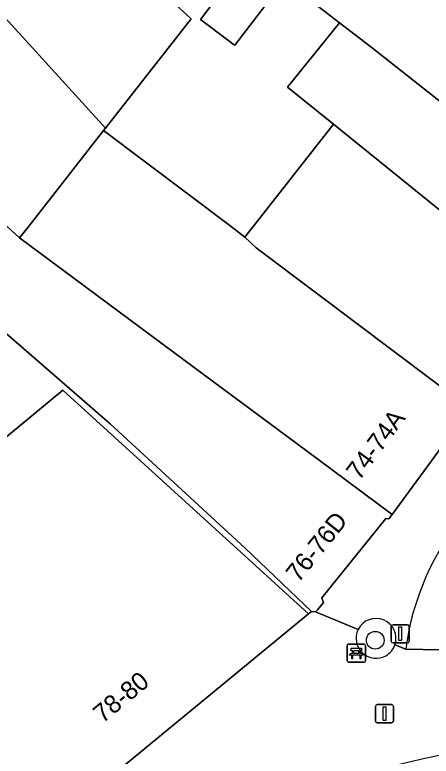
# Model space of a CAD drawing. Extents: x 160663 to 161506, y 382245 to 383291.
# Drawn here: x 160983.36 to 161006.23, y 382930.82 to 382971.53 of the extents above; entities that cross this region are included whole.
import ezdxf

# ---------------------------------------------------------------- set-up
doc = ezdxf.new("R2010")
doc.units = 0
for name, color, linetype in [('IMGEO_Bank', 7, 'Continuous'), ('IMGEO_Boom', 7, 'Continuous'), ('IMGEO_Erf', 7, 'Continuous'), ('IMGEO_Groenvoorziening', 7, 'Continuous'), ('IMGEO_Pand', 7, 'Continuous'), ('IMGEO_Pand_nummerreeks', 7, 'Continuous'), ('IMGEO_Rijbaan_lokaal_gesloten', 7, 'Continuous'), ('IMGEO_Verkeersregelinstallatiepaal', 7, 'Continuous'), ('IMGEO_Voetpad_open', 7, 'Continuous'), ('IMGEO_Woonerf_open', 7, 'Continuous')]:
    doc.layers.add(name, color=color, linetype=linetype)

msp = doc.modelspace()

# ---------------------------------------------------------------- linework, layer by layer
at = {"layer": 'IMGEO_Bank'}
for p, q in [((161001.621, 382936.055), (161001.621, 382936.896)), ((161001.621, 382936.896), (161001.621, 382936.055)), ((161001.696, 382936.98), (161002.537, 382936.98)), ((161002.537, 382936.98), (161001.696, 382936.98)), ((161002.621, 382936.905), (161002.621, 382936.064)), ((161002.621, 382936.064), (161002.621, 382936.905)), ((161001.93, 382936.486), (161001.93, 382936.592)), ((161001.974, 382936.592), (161001.974, 382936.486)), ((161002.262, 382936.598), (161001.98, 382936.598)), ((161001.98, 382936.48), (161002.262, 382936.48)), ((161002.268, 382936.486), (161002.268, 382936.592)), ((161002.312, 382936.592), (161002.312, 382936.486)), ((161002.318, 382936.378), (161001.925, 382936.378)), ((161002.546, 382935.98), (161001.705, 382935.98)), ((161001.705, 382935.98), (161002.546, 382935.98))]:
    msp.add_line(p, q, dxfattribs=at)
for points in [[(161001.868, 382936.378), (161001.726, 382936.378), (161001.838, 382936.48), (161001.924, 382936.48)], [(161001.924, 382936.598), (161001.838, 382936.598), (161001.838, 382936.759), (161002.401, 382936.759), (161002.401, 382936.598), (161002.318, 382936.598)], [(161002.318, 382936.48), (161002.401, 382936.48), (161002.513, 382936.378), (161002.374, 382936.378)], [(161001.918, 382936.371), (161001.918, 382936.164), (161001.875, 382936.164), (161001.875, 382936.371)], [(161002.368, 382936.371), (161002.368, 382936.164), (161002.324, 382936.164), (161002.324, 382936.371)]]:
    msp.add_lwpolyline(points, dxfattribs=at)
for centre, radius, start, end in [((161001.699, 382936.902), 0.0779, 92.4484, 184.2845), ((161001.699, 382936.902), 0.0779, 92.4484, 184.2845), ((161002.543, 382936.902), 0.0779, 2.4484, 94.2845), ((161002.543, 382936.902), 0.0779, 2.4484, 94.2845), ((161001.923, 382936.591), 0.00671, 2.8957, 87.1043), ((161001.923, 382936.487), 0.00671, 272.8957, 357.1043), ((161001.98, 382936.591), 0.00671, 92.8957, 177.1043), ((161001.98, 382936.487), 0.00671, 182.8957, 267.1043), ((161002.262, 382936.591), 0.00671, 2.8957, 87.1043), ((161002.262, 382936.487), 0.00671, 272.8957, 357.1043), ((161002.319, 382936.591), 0.00671, 92.8957, 177.1043), ((161002.319, 382936.487), 0.00671, 182.8957, 267.1043), ((161001.868, 382936.371), 0.00671, 2.8957, 87.1043), ((161001.925, 382936.371), 0.00671, 92.8957, 177.1043), ((161002.317, 382936.371), 0.00671, 2.8957, 87.1043), ((161002.374, 382936.371), 0.00671, 92.8957, 177.1043), ((161002.543, 382936.058), 0.0779, 272.4484, 4.2845), ((161002.543, 382936.058), 0.0779, 272.4484, 4.2845), ((161001.699, 382936.058), 0.0779, 182.4484, 274.2845), ((161001.699, 382936.058), 0.0779, 182.4484, 274.2845)]:
    msp.add_arc(centre, radius, start, end, dxfattribs=at)
at = {"layer": 'IMGEO_Boom'}
msp.add_circle((161003.16, 382937.188), 0.489, dxfattribs=at)
at = {"layer": 'IMGEO_Erf'}
for points in [[(160982.974, 382980.502), (160993.051, 382971.304), (160988.34, 382965.314), (160988.236, 382965.181), (160995.173, 382959.957), (160995.993, 382959.316), (161000, 382964.424), (161000.86, 382965.52), (161000.024, 382966.196), (160998.342, 382967.555), (161001.199, 382971.092), (161000, 382972.012)], [(160958.423, 382973.784), (160961.617, 382969.937), (160953.589, 382963.329), (160956.311, 382959.971), (160964.447, 382966.667), (160967.625, 382962.807), (160980.882, 382946.7), (160986.008, 382950.919), (160995.794, 382942.001), (160999.488, 382938.635), (160999.653, 382938.77), (160996.011, 382942.24), (160988.597, 382949.072), (160977.411, 382958.766), (160978.16, 382959.63), (160975.601, 382961.849), (160977.888, 382964.488), (160978.517, 382965.213), (160973.196, 382970.113), (160978.583, 382975.62)], [(160998.15, 382973.423), (160995.446, 382969.858), (160995.377, 382969.91), (160995.111, 382970.112), (160993.565, 382971.284), (160996.082, 382974.605)]]:
    msp.add_lwpolyline(points, dxfattribs=at)
at = {"layer": 'IMGEO_Groenvoorziening'}
for centre, radius, start, end in [((161003.203, 382937.292), 1.096, 341.2814, 153.8415), ((161003.203, 382937.292), 1.096, 153.86, 299.7753), ((161003.207, 382937.289), 1.091, 299.6501, 341.3246)]:
    msp.add_arc(centre, radius, start, end, dxfattribs=at)
at = {"layer": 'IMGEO_Pand'}
for points in [[(161021.889, 382983.539), (161021.424, 382982.963), (161020.229, 382981.484), (161010.392, 382990.267), (161006.384, 382993.846), (161001.288, 382998.396), (161000, 382996.936), (160993.87, 382988.888), (160992.195, 382990.157), (160991.683, 382990.545), (160984.163, 382980.616), (160988.149, 382977.597), (160992.662, 382974.178), (160994.341, 382976.392), (160996.094, 382974.99), (160996.272, 382974.854), (160997.96, 382973.567), (160998.081, 382973.475), (160998.15, 382973.423), (161000, 382972.012), (161001.199, 382971.092), (161002.915, 382969.775), (161015.758, 382959.65), (161029.997, 382977.303)], [(160982.974, 382980.502), (160978.741, 382975.864), (160978.78, 382975.821), (160988.34, 382965.314), (160993.051, 382971.304)], [(160978.78, 382975.821), (160978.583, 382975.62), (160973.196, 382970.113), (160978.517, 382965.213), (160977.888, 382964.488), (160983.601, 382959.296), (160983.622, 382959.281), (160984.019, 382959.789), (160988.236, 382965.181), (160988.34, 382965.314)], [(160998.15, 382973.423), (160998.081, 382973.475), (160997.96, 382973.567), (160996.272, 382974.854), (160996.082, 382974.605), (160993.565, 382971.284), (160995.111, 382970.112), (160995.377, 382969.91), (160995.446, 382969.858)], [(161002.915, 382969.775), (161001.199, 382971.092), (160998.342, 382967.555), (161000.024, 382966.196), (161000.86, 382965.52), (161012.752, 382955.909), (161012.871, 382956.071), (161015.758, 382959.65)], [(160967.625, 382962.807), (160964.447, 382966.667), (160956.311, 382959.971), (160956.597, 382959.624), (160969.413, 382944.053), (160975.966, 382936.092), (160977.597, 382934.11), (160984.218, 382926.066), (160984.598, 382926.379), (160999.488, 382938.635), (160995.794, 382942.001), (160986.008, 382950.919), (160980.882, 382946.7)], [(161000.86, 382965.52), (161000, 382964.424), (160995.993, 382959.316), (160996.619, 382958.737), (161000, 382956.191), (161008.347, 382949.906), (161008.545, 382950.176), (161012.752, 382955.909)], [(161000, 382956.191), (160996.619, 382958.737), (160995.993, 382959.316), (160995.173, 382959.957), (160988.236, 382965.181), (160984.019, 382959.789), (160983.622, 382959.281), (160992.088, 382953), (161000, 382947.131), (161004.086, 382944.1), (161008.347, 382949.906)], [(160992.088, 382953), (160983.622, 382959.281), (160983.601, 382959.296), (160977.888, 382964.488), (160975.601, 382961.849), (160978.16, 382959.63), (160977.411, 382958.766), (160988.597, 382949.072), (160996.011, 382942.24), (160999.653, 382938.77), (160999.879, 382938.742), (161000, 382938.882), (161000.324, 382939.258), (161000.226, 382939.512), (161003.75, 382943.874), (161003.903, 382943.85), (161004.086, 382944.1), (161000, 382947.131)]]:
    msp.add_lwpolyline(points, close=True, dxfattribs=at)
at = {"layer": 'IMGEO_Rijbaan_lokaal_gesloten'}
msp.add_arc((161021.311, 382862.511), 69.907, 98.05719, 106.40828, dxfattribs=at)
at = {"layer": 'IMGEO_Verkeersregelinstallatiepaal'}
for p, q in [((161004.038, 382937.141), (161004.038, 382937.941)), ((161004.038, 382937.941), (161004.038, 382937.141)), ((161004.138, 382938.041), (161004.928, 382938.041)), ((161004.928, 382938.041), (161004.138, 382938.041)), ((161005.028, 382937.941), (161005.028, 382937.141)), ((161005.028, 382937.141), (161005.028, 382937.941)), ((161004.928, 382937.041), (161004.138, 382937.041)), ((161004.138, 382937.041), (161004.928, 382937.041)), ((161003.272, 382933.652), (161004.062, 382933.652)), ((161004.062, 382933.652), (161003.272, 382933.652)), ((161003.172, 382932.752), (161003.172, 382933.552)), ((161003.172, 382933.552), (161003.172, 382932.752)), ((161004.162, 382933.552), (161004.162, 382932.752)), ((161004.162, 382932.752), (161004.162, 382933.552)), ((161004.062, 382932.652), (161003.272, 382932.652)), ((161003.272, 382932.652), (161004.062, 382932.652))]:
    msp.add_line(p, q, dxfattribs=at)
for points in [[(161004.458, 382937.916), (161004.608, 382937.916), (161004.608, 382937.166), (161004.458, 382937.166), (161004.458, 382937.916)], [(161003.592, 382933.527), (161003.742, 382933.527), (161003.742, 382932.777), (161003.592, 382932.777), (161003.592, 382933.527)]]:
    msp.add_lwpolyline(points, dxfattribs=at)
for centre, start, end in [((161004.138, 382937.941), 90, 180), ((161004.138, 382937.941), 90, 180), ((161004.928, 382937.941), 0, 90), ((161004.928, 382937.941), 360, 90), ((161004.138, 382937.141), 180, 270), ((161004.138, 382937.141), 180, 270), ((161004.928, 382937.141), 270, 0), ((161004.928, 382937.141), 270, 0), ((161003.272, 382933.552), 90, 180), ((161003.272, 382933.552), 90, 180), ((161004.062, 382933.552), 0, 90), ((161004.062, 382933.552), 360, 90), ((161003.272, 382932.752), 180, 270), ((161003.272, 382932.752), 180, 270), ((161004.062, 382932.752), 270, 0), ((161004.062, 382932.752), 270, 0)]:
    msp.add_arc(centre, 0.1, start, end, dxfattribs=at)
at = {"layer": 'IMGEO_Voetpad_open'}
for points in [[(161008.347, 382949.906), (161004.086, 382944.1), (161003.903, 382943.85), (161003.75, 382943.874), (161000.226, 382939.512), (161000.324, 382939.258), (161000, 382938.882), (160999.879, 382938.742), (161002.219, 382937.775)], [(161002.219, 382937.775), (160999.879, 382938.742), (160999.653, 382938.77), (160999.488, 382938.635), (160984.598, 382926.379), (160985.439, 382925.133), (160986.15, 382924.079)], [(161009.543, 382936.615), (161004.833, 382936.695), (161004.241, 382936.94)], [(161004.241, 382936.94), (161004.833, 382936.695)]]:
    msp.add_lwpolyline(points, dxfattribs=at)
for centre, radius, start, end in [((161019.375, 382934.767), 14.67, 140.041, 172.4461), ((161003.203, 382937.292), 1.096, 341.2814, 153.8415), ((161003.203, 382937.292), 1.096, 153.86, 299.7753), ((161003.207, 382937.289), 1.091, 299.6501, 341.3246), ((161021.311, 382862.511), 69.907, 98.05719, 106.40828)]:
    msp.add_arc(centre, radius, start, end, dxfattribs=at)
at = {"layer": 'IMGEO_Woonerf_open'}
msp.add_lwpolyline([(161004.833, 382936.695), (161009.543, 382936.615)], dxfattribs=at)
msp.add_arc((161019.375, 382934.767), 14.67, 140.041, 172.4461, dxfattribs=at)

# ---------------------------------------------------------------- texts
at = {"layer": 'IMGEO_Pand_nummerreeks'}
for s, rotation, p in [('74-74A', 53.4913, (161002.293, 382945.916)), ('76-76D', 51.0677, (160998.945, 382940.314)), ('78-80', 39.4596, (160988.187, 382932.598))]:
    msp.add_text(s, height=1, rotation=rotation, dxfattribs=at).set_placement(p)

doc.saveas('drawing.dxf')
